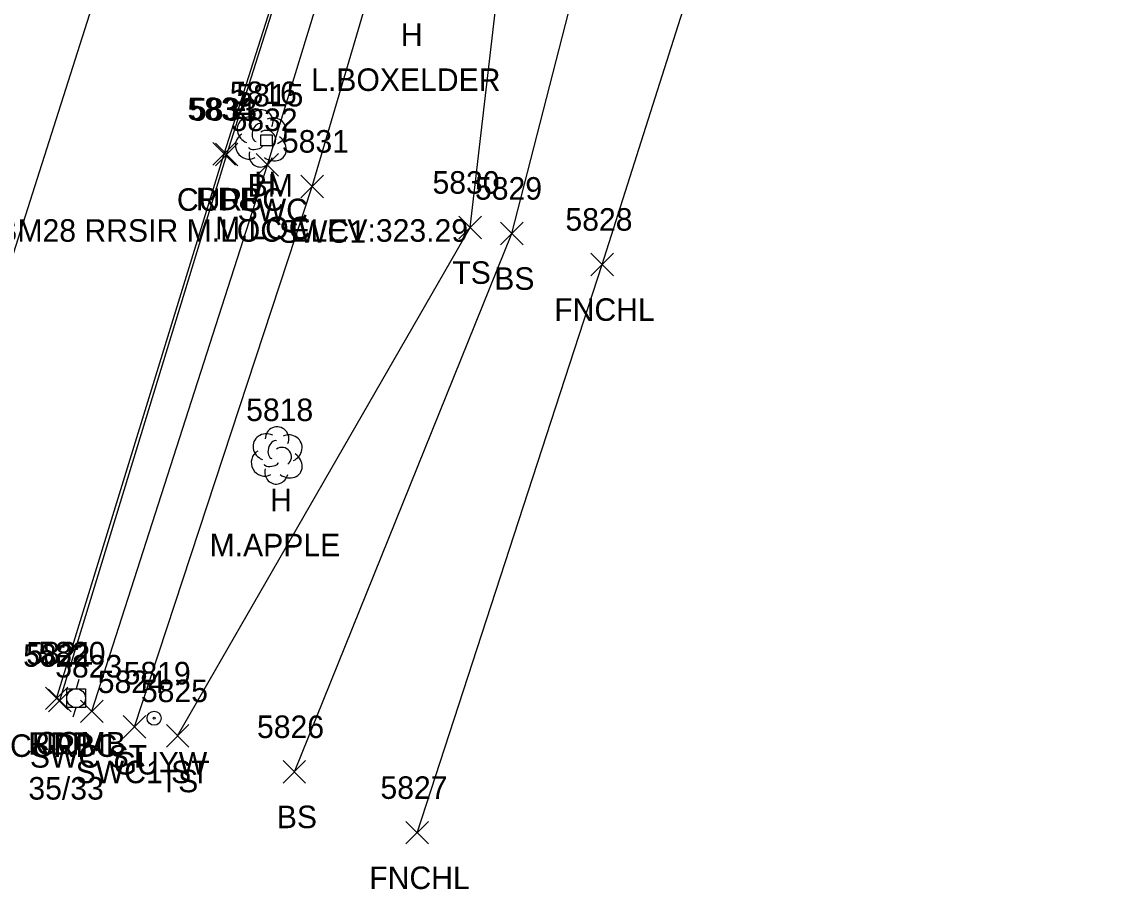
# Model space of a CAD drawing. Extents: x 1462089 to 1464015, y 730534 to 736144.
# Drawn here: x 1462370.3 to 1462466.3, y 730533.6 to 730610.6 of the extents above; entities that cross this region are included whole.
import ezdxf

# ---------------------------------------------------------------- set-up
doc = ezdxf.new("R2010")
doc.units = 0
for name, color, linetype in [('C_A', 7, 'Continuous'), ('C_C', 7, 'Continuous'), ('C_I', 7, 'Continuous'), ('CPBM', 7, 'Continuous'), ('L_A', 7, 'Continuous'), ('L_C', 7, 'Continuous'), ('L_I', 7, 'Continuous'), ('L_TIC', 7, 'Continuous'), ('LELB', 7, 'Continuous'), ('LFNC', 7, 'Continuous'), ('LTD', 7, 'Continuous'), ('P_A', 7, 'Continuous'), ('P_I', 7, 'Continuous'), ('P_TIC', 7, 'Continuous'), ('PET', 7, 'Continuous'), ('PRC', 7, 'Continuous'), ('R_A', 7, 'Continuous'), ('R_I', 7, 'Continuous'), ('R_TIC', 7, 'Continuous'), ('RC', 7, 'Continuous'), ('RSW', 7, 'Continuous'), ('U_A', 7, 'Continuous'), ('U_C', 7, 'Continuous'), ('U_I', 7, 'Continuous'), ('UP', 7, 'Continuous'), ('UPGW', 7, 'Continuous')]:
    doc.layers.add(name, color=color, linetype=linetype)

msp = doc.modelspace()

# ---------------------------------------------------------------- linework, layer by layer
at = {"layer": 'CPBM'}
for p, q in [((1462391.576, 730599.594), (1462391.576, 730600.594)), ((1462391.576, 730600.594), (1462392.576, 730600.594)), ((1462392.078, 730600.095), (1462392.078, 730600.095)), ((1462392.078, 730600.095), (1462392.078, 730600.095)), ((1462392.576, 730600.594), (1462392.576, 730599.594)), ((1462392.576, 730599.594), (1462391.576, 730599.594))]:
    msp.add_line(p, q, dxfattribs=at)
at = {"layer": 'L_TIC'}
for points in [[(1462409.14, 730591.357), (1462411.14, 730593.357)], [(1462411.14, 730591.357), (1462409.14, 730593.357)], [(1462412.831, 730590.827), (1462414.831, 730592.827)], [(1462414.831, 730590.827), (1462412.831, 730592.827)], [(1462420.846, 730588.074), (1462422.846, 730590.074)], [(1462422.846, 730588.074), (1462420.846, 730590.074)], [(1462383.18, 730546.242), (1462385.18, 730548.242)], [(1462385.18, 730546.242), (1462383.18, 730548.242)], [(1462393.536, 730543.056), (1462395.536, 730545.056)], [(1462395.536, 730543.056), (1462393.536, 730545.056)], [(1462404.433, 730537.655), (1462406.433, 730539.655)], [(1462406.433, 730537.655), (1462404.433, 730539.655)]]:
    msp.add_lwpolyline(points, dxfattribs=at)
at = {"layer": 'LELB'}
for points in [[(1462384.18, 730547.242), (1462410.14, 730592.357), (1462415.369, 730637.443), (1462421.493, 730656.015), (1462426.438, 730673.437)], [(1462394.536, 730544.056), (1462413.831, 730591.827), (1462424.777, 730634.476), (1462434.658, 730650.764), (1462440.56, 730650.16), (1462454.565, 730642.497)]]:
    msp.add_lwpolyline(points, dxfattribs=at)
at = {"layer": 'LFNC'}
msp.add_lwpolyline([(1462405.433, 730538.655), (1462421.846, 730589.074), (1462439.882, 730645.841)], dxfattribs=at)
at = {"layer": 'LTD'}
for p, q in [((1462391.553, 730600.312), (1462391.553, 730600.312)), ((1462391.553, 730600.312), (1462391.553, 730600.312)), ((1462392.953, 730572.181), (1462392.953, 730572.181)), ((1462392.953, 730572.181), (1462392.953, 730572.181))]:
    msp.add_line(p, q, dxfattribs=at)
for centre in [(1462391.599, 730601.746), (1462393, 730573.615)]:
    msp.add_arc(centre, 1.047, 335.52715, 180.95627, dxfattribs=at)
for centre, major_axis, ratio, start_param, end_param in [((1462390.761, 730600.979), (1.21, -0.512), 0.895232, 1.570796, 4.712389), ((1462391.344, 730600.77), (-0.208, -0.792), 0.645439, 3.141593, 6.283185), ((1462392.594, 730600.896), (-1.141, -0.483), 0.949671, 1.570796, 4.712389), ((1462390.469, 730599.604), (0.584, -1.042), 0.959034, 3.141593, 6.283185), ((1462392.053, 730600.146), (-0.5, 0.667), 0.989748, 3.141593, 6.283185), ((1462392.553, 730599.479), (-1.09, 0.792), 0.841452, 1.570796, 4.712389), ((1462391.553, 730598.812), (0.265, 1.061), 0.942809, 1.570796, 4.712389), ((1462391.094, 730599.562), (-0.625, -0.083), 0.423636, 0, 3.141593), ((1462392.161, 730572.848), (1.21, -0.512), 0.895232, 1.570796, 4.712389), ((1462393.994, 730572.765), (-1.141, -0.483), 0.949671, 1.570796, 4.712389), ((1462392.745, 730572.64), (-0.208, -0.792), 0.645439, 3.141593, 6.283185), ((1462393.453, 730572.015), (-0.5, 0.667), 0.989748, 3.141593, 6.283185), ((1462391.87, 730571.473), (0.584, -1.042), 0.959034, 3.141593, 6.283185), ((1462393.953, 730571.348), (-1.09, 0.792), 0.841452, 1.570796, 4.712389), ((1462392.953, 730570.681), (0.265, 1.061), 0.942809, 1.570796, 4.712389), ((1462392.495, 730571.431), (-0.625, -0.083), 0.423636, 0, 3.141593)]:
    msp.add_ellipse(centre, major_axis=major_axis, ratio=ratio, start_param=start_param, end_param=end_param, dxfattribs=at)
at = {"layer": 'P_TIC'}
for points in [[(1462387.309, 730597.891), (1462389.309, 730599.891)], [(1462389.309, 730597.891), (1462387.309, 730599.891)], [(1462372.445, 730549.573), (1462374.445, 730551.573)], [(1462374.445, 730549.573), (1462372.445, 730551.573)]]:
    msp.add_lwpolyline(points, dxfattribs=at)
at = {"layer": 'PET'}
msp.add_lwpolyline([(1462373.445, 730550.573), (1462388.309, 730598.891), (1462401.963, 730641.783), (1462433.168, 730744.632), (1462438.196, 730760.147), (1462452.976, 730810.554), (1462463.625, 730846.159), (1462471.864, 730873.588), (1462478.576, 730896.599), (1462485.477, 730919.066), (1462495.517, 730952.686), (1462508.095, 730994.119), (1462517.419, 731025.054), (1462526.796, 731054.959), (1462537.856, 731087.551), (1462549.797, 731117.253), (1462553.734, 731129.646)], dxfattribs=at)
at = {"layer": 'PRC'}
msp.add_lwpolyline([(1462531.515, 731132.984), (1462517.28, 731085.282), (1462509.353, 731045.029), (1462493.599, 730992.368), (1462476.953, 730933.085), (1462462.375, 730883.835), (1462447.905, 730837.268), (1462435.369, 730797.923), (1462416.948, 730748.336), (1462410.801, 730719.379), (1462396.341, 730673.49), (1462394.762, 730664.922), (1462379.239, 730620.511), (1462379.284, 730620.518), (1462366.634, 730580.828), (1462357.577, 730553.747)], dxfattribs=at)
at = {"layer": 'R_TIC'}
for points in [[(1462387.532, 730597.837), (1462389.532, 730599.837)], [(1462389.532, 730597.837), (1462387.532, 730599.837)], [(1462391.14, 730596.919), (1462393.14, 730598.919)], [(1462393.14, 730596.919), (1462391.14, 730598.919)], [(1462395.125, 730595.001), (1462397.125, 730597.001)], [(1462397.125, 730595.001), (1462395.125, 730597.001)], [(1462372.731, 730549.381), (1462374.731, 730551.381)], [(1462374.731, 730549.381), (1462372.731, 730551.381)], [(1462375.574, 730548.426), (1462377.574, 730550.426)], [(1462377.574, 730548.426), (1462375.574, 730550.426)], [(1462379.351, 730547.047), (1462381.351, 730549.047)], [(1462381.351, 730547.047), (1462379.351, 730549.047)]]:
    msp.add_lwpolyline(points, dxfattribs=at)
at = {"layer": 'RC'}
msp.add_lwpolyline([(1462373.731, 730550.381), (1462388.532, 730598.837), (1462402.208, 730641.896)], dxfattribs=at)
at = {"layer": 'RSW'}
for points in [[(1462376.574, 730549.426), (1462392.14, 730597.919), (1462405.356, 730640.993)], [(1462380.351, 730548.047), (1462396.125, 730596.001), (1462409.048, 730639.916)]]:
    msp.add_lwpolyline(points, dxfattribs=at)
at = {"layer": 'UP'}
for p, q in [((1462375.424, 730552.259), (1462375.174, 730551.425)), ((1462374.34, 730549.759), (1462374.34, 730551.425)), ((1462374.34, 730551.425), (1462376.007, 730551.425)), ((1462376.007, 730551.425), (1462376.007, 730549.759)), ((1462376.007, 730549.759), (1462374.34, 730549.759)), ((1462374.924, 730548.925), (1462375.174, 730549.759)), ((1462375.174, 730550.592), (1462375.174, 730550.592))]:
    msp.add_line(p, q, dxfattribs=at)
msp.add_circle((1462375.174, 730550.592), 0.833, dxfattribs=at)
at = {"layer": 'UPGW'}
for radius in [0.625, 0.0833]:
    msp.add_circle((1462382.092, 730548.815), radius, dxfattribs=at)

# ---------------------------------------------------------------- texts
at = {"layer": 'C_A'}
msp.add_text('BM', height=2, dxfattribs=at).set_placement((1462390.393, 730595.095))
at = {"layer": 'C_C'}
msp.add_text('BM28 RRSIR M.LOC ELEV:323.29', height=2, dxfattribs=at).set_placement((1462368.181, 730591.095))
at = {"layer": 'C_I'}
msp.add_text('5815', height=2, dxfattribs=at).set_placement((1462389.386, 730603.095))
at = {"layer": 'L_A'}
for s, p in [('H', (1462403.987, 730608.475)), ('H', (1462390.986, 730595.312)), ('TS', (1462408.55, 730587.357)), ('BS', (1462412.272, 730586.827)), ('FNCHL', (1462417.594, 730584.074)), ('H', (1462392.386, 730567.181)), ('TS', (1462382.59, 730542.242)), ('BS', (1462392.977, 730539.056)), ('FNCHL', (1462401.181, 730533.655))]:
    msp.add_text(s, height=2, dxfattribs=at).set_placement(p)
at = {"layer": 'L_C'}
for s, p in [('L.BOXELDER', (1462396.027, 730604.475)), ('M.LOC', (1462387.498, 730591.312)), ('M.APPLE', (1462387.016, 730563.181))]:
    msp.add_text(s, height=2, dxfattribs=at).set_placement(p)
at = {"layer": 'L_I'}
for s, p in [('5816', (1462388.805, 730603.312)), ('5830', (1462406.794, 730595.357)), ('5829', (1462410.563, 730594.827)), ('5828', (1462418.586, 730592.074)), ('5818', (1462390.26, 730575.181)), ('5825', (1462380.921, 730550.242)), ('5826', (1462391.221, 730547.056)), ('5827', (1462402.173, 730541.655))]:
    msp.add_text(s, height=2, dxfattribs=at).set_placement(p)
at = {"layer": 'P_A'}
for p in [(1462385.797, 730593.891), (1462370.933, 730545.573)]:
    msp.add_text('RDP', height=2, dxfattribs=at).set_placement(p)
at = {"layer": 'P_I'}
for s, p in [('5834', (1462385.05, 730601.891)), ('5821', (1462370.752, 730553.573))]:
    msp.add_text(s, height=2, dxfattribs=at).set_placement(p)
at = {"layer": 'R_A'}
for s, p in [('CURBC', (1462384.114, 730593.837)), ('SWC', (1462389.502, 730592.919)), ('SWC1', (1462393.164, 730591.001)), ('CURBC', (1462369.314, 730545.381)), ('SWC ST', (1462371.07, 730544.426)), ('SWC1 ST', (1462375.131, 730543.047))]:
    msp.add_text(s, height=2, dxfattribs=at).set_placement(p)
at = {"layer": 'R_I'}
for s, p in [('5833', (1462385.272, 730601.837)), ('5832', (1462388.88, 730600.919)), ('5831', (1462393.432, 730599.001)), ('5822', (1462370.472, 730553.381)), ('5823', (1462373.314, 730552.426)), ('5824', (1462377.091, 730551.047))]:
    msp.add_text(s, height=2, dxfattribs=at).set_placement(p)
at = {"layer": 'U_A'}
for s, p in [('COMB', (1462371.56, 730545.592)), ('GUYW', (1462378.486, 730543.815))]:
    msp.add_text(s, height=2, dxfattribs=at).set_placement(p)
at = {"layer": 'U_C'}
msp.add_text('35/33', height=2, dxfattribs=at).set_placement((1462370.938, 730541.592))
at = {"layer": 'U_I'}
for s, p in [('5820', (1462371.827, 730553.592)), ('5819', (1462379.392, 730551.815))]:
    msp.add_text(s, height=2, dxfattribs=at).set_placement(p)

doc.saveas('drawing.dxf')
